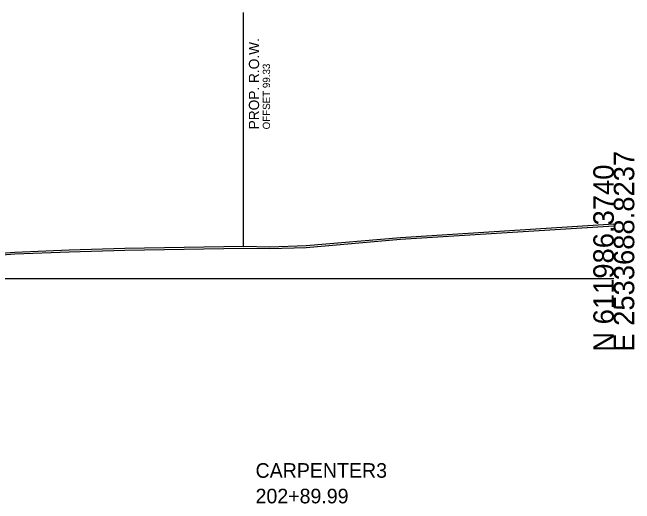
# Model space of a CAD drawing. Extents: x -120 to 2876, y -25 to 8560.
# Drawn here: x 1517.7 to 1602.8, y 969.2 to 1036.4 of the extents above; entities that cross this region are included whole.
import ezdxf

# ---------------------------------------------------------------- set-up
doc = ezdxf.new("R2010")
doc.units = 0
for name, color, linetype in [('DESIGN - ROW - Right-of-Way and Easement Labels', 7, 'Continuous'), ('DESIGN - ROW - Right-of-Way Linework', 7, 'Continuous'), ('DESIGN - SHEET - Light Grid', 7, 'Continuous'), ('DESIGN - TYPICAL - Warning Text', 7, 'Continuous'), ('SURVEY - GROUND - Bottom of Topsoil Layer', 7, 'Continuous'), ('SURVEY - GROUND - Top of Ground', 7, 'Continuous')]:
    doc.layers.add(name, color=color, linetype=linetype)

msp = doc.modelspace()

# ---------------------------------------------------------------- linework, layer by layer
at = {"layer": 'DESIGN - ROW - Right-of-Way Linework'}
msp.add_line((1549.334, 1004.422), (1549.334, 1036.422), dxfattribs=at)
at = {"layer": 'DESIGN - SHEET - Light Grid'}
msp.add_line((1450, 1000), (1600, 1000), dxfattribs=at)
at = {"layer": 'SURVEY - GROUND - Bottom of Topsoil Layer'}
for p, q in [((1570.804, 1005.381), (1600, 1007.235)), ((1557.911, 1004.272), (1570.804, 1005.381)), ((1533.124, 1003.916), (1549.347, 1004.172)), ((1549.347, 1004.172), (1552.958, 1004.112)), ((1552.958, 1004.112), (1557.911, 1004.272)), ((1503.737, 1002.353), (1518.07, 1003.38)), ((1518.07, 1003.38), (1525.495, 1003.681)), ((1525.495, 1003.681), (1533.124, 1003.916))]:
    msp.add_line(p, q, dxfattribs=at)
at = {"layer": 'SURVEY - GROUND - Top of Ground'}
msp.add_lwpolyline([(1503.737, 1002.603), (1518.07, 1003.63), (1525.495, 1003.931), (1533.124, 1004.166), (1549.347, 1004.422), (1552.958, 1004.362), (1557.911, 1004.522), (1570.804, 1005.631), (1600, 1007.485)], dxfattribs=at)

# ---------------------------------------------------------------- texts
at = {"layer": 'DESIGN - ROW - Right-of-Way and Easement Labels'}
for s, height, p in [('PROP. R.O.W.', 1.4, (1551.484, 1020.422)), ('OFFSET 99.33', 1, (1552.984, 1020.422))]:
    msp.add_text(s, height=height, rotation=90, dxfattribs=at).set_placement(p)
at = {"layer": 'DESIGN - SHEET - Light Grid'}
for s, p in [('E 2533688.8237', (1602.8, 990)), ('N 611986.3740', (1600, 990))]:
    msp.add_text(s, height=2.8, rotation=90, dxfattribs=at).set_placement(p)
at = {"layer": 'DESIGN - TYPICAL - Warning Text'}
for s, p in [('CARPENTER3', (1551, 972.75)), ('202+89.99', (1551, 969.25))]:
    msp.add_text(s, height=2, dxfattribs=at).set_placement(p)

doc.saveas('drawing.dxf')
